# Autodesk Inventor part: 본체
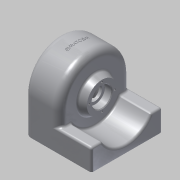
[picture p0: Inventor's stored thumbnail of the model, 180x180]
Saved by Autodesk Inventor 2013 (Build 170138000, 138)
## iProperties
Created: 2015-02
Part Number: 본체
Material: 알루미늄 6061
Document SubType Name: Modeling
Designer: Administrator
Density: 1 g/cm^3
Author: Administrator
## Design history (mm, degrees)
sketch "스케치1"
  geometry: L1 (-34.5, 0)-(34.5, 0); L2 (-34.5, 14)-(-34.5, 21.36); L3 (-34.5, 21.36)-(-24.5, 25); L4 (-24.5, 25)-(-24.5, 50); L5 (-24.5, 50)-(25.5, 50); L6 (25.5, 50)-(25.5, 20); L7 (25.5, 20)-(34.5, 20); L8 (34.5, 20)-(34.5, 0); L9 (34.5, 0)-(31.5, 0); L10 (31.5, 0)-(31.5, 10); L11 (31.5, 10)-(29.5, 10); L12 (29.5, 10)-(29.5, 14); L13 (29.5, 14)-(21.5, 14); L14 (21.5, 14)-(21.5, 46); L15 (21.5, 46)-(-20.5, 46); L16 (-20.5, 46)-(-20.5, 10); L17 (-20.5, 10)-(-24.5, 10); L18 (-24.5, 10)-(-24.5, 14); L19 (-24.5, 14)-(-34.5, 14); 3 further points
  constraints: 38 end point, 9 parallel, 4 perpendicular, 2 coincident, 2 horizontal, 2 midpoint, 1 collinear, 1 point on line, 1 vertical, 1 vertical alignment
  dimensions: "d0" = 69 distance of L1.start L1.end; "d1" = 20 diameter of L17 L1; "d2" = 28 diameter of L19 L1; "d3" = 50 diameter of L3.end L1; "d4" = 100 diameter of L5 L1; "d5" = 10 distance between parallel lines of L2 L4; "d6" = 50 distance of L4.end L5.end; "d7" = 40 diameter of L7 L1; "d8" = 20 diameter of L11 L1; "d9" = 28 diameter of L13 L1; "d10" = 2 distance between parallel lines of L10 L12; "d11" = 8 distance of L12.end L13.end; "d12" = 42 distance of L14.end L15.end; "d13" = 10 distance of L18.end L2.start; "d14" = 4 distance of L16.end L17.end; "d15" = 92 diameter of L15 L1; "d16" = 110 deg angle of L3 L4
revolve "회전1" sketch "스케치1" stored, may be unused: angle "d17" = 90 deg
sketch "스케치3"
  geometry: L1 (0, 50)-(50, 50); L2 (50, 50)-(50, -50); L3 (50, -50)-(0, -50); A1 r 50 centre (0, 0) between (0, 50) and (0, -50) reference
  constraints: 6 end point, 2 point on circle, 2 tangent, 1 horizontal, 1 perpendicular
  dimensions: "d18" = 50 distance of L1.start L1.end; "d19" = 100 distance of L1.end L2.end
extrude "돌출1" join sketch "스케치3" distance "d20" = 50; taper "d21" = 0 deg
sketch "스케치4"
  geometry: L1 (0, 100)-(50, 100) reference; L2 (0, 0)-(0, 100) reference; L3 (4, 96)-(46, 96); L4 (46, 96)-(46, 4); L5 (46, 4)-(4, 4); L6 (4, 4)-(4, 96); 1 further point
  constraints: 8 end point, 2 parallel, 1 horizontal, 1 perpendicular
  dimensions: "d22" = 42 distance of L4.end L5.end; "d23" = 92 distance of L3.end L4.end; "d24" = 4 distance between parallel lines of L2 L6; "d25" = 4 distance between parallel lines of L1 L3
extrude "돌출2" cut sketch "스케치4" distance "d26" = 50; taper "d27" = 0 deg
sketch "스케치5"
  geometry: L1 (-50, 0)-(0, 0) reference; L2 (0, 0)-(0, 100) reference; L3 (0, 100)-(-50, 100) reference; L4 (-30, 84.641)-(-30, 100); L5 (-30, 15.359)-(-30, 0); C1 r 25 at (-50, 50) reference; A1 r 40 centre (-50, 50) between (-30, 15.359) and (-30, 84.641)
  constraints: 4 end point, 2 perpendicular, 2 point on circle, 2 point on line, 1 centre point, 1 coincident, 1 collinear
  dimensions: "d28" = 80 diameter of A1; "d29" = 30 distance between parallel lines of L2 L4
extrude "돌출3" join sketch "스케치5" distance "d30" = 45; taper "d31" = 0 deg
node "작업 평면1"
sketch "스케치6"
  geometry: L1 (-25, 50)-(-25, -50) reference; 2 further points
  constraints: 1 horizontal alignment, 1 other
  dimensions: "d32" = 25 distance from line of L1 point (0, 0)
feature "엠보싱1" sketch "스케치6" dims "d33" = 0.5, "d34" = 0
fillet "모깎기1" dims "d35" = 10
fillet "모깎기2" dims "d36" = 6
fillet "모깎기3" dims "d37" = 0.3
chamfer "모따기1" distance "d38" = 1; stored, may be unused: second distance "d39" = 2, angle "d40" = 45 deg
fillet "모깎기4" dims "d41" = 3
fillet "모깎기5" dims "d42" = 3
fillet "모깎기6" dims "d43" = 3
sketch "스케치7" dims "d44" = 36
  geometry: C1 r 15 at (0, 0) reference; 5 further points
  constraints: 2 vertical alignment, 1 coincident, 7 other
  dimensions: "d47" = 360 deg dimension on point (0, 0) point (0, 18) (derived)
hole "구멍1" sketch "스케치7" at (0, 18), (-18, 0), (0, -18), (18, 0) diameter "d49" = 2.459; stored, may be unused: countersink angle "d53" = 90 deg, drill point angle "d55" = 118 deg; dims "d50" = 6, "d51" = 4, "d52" = 2, "d54" = 9
sketch "스케치8"
  geometry: L1 (-95, -7)-(-95, 87) reference; L2 (-86, 81.75)-(-53, 81.75); L3 (-53, 81.75)-(-53, -1.75); L4 (-53, -1.75)-(-86, -1.75); L5 (-86, -1.75)-(-86, 81.75); 7 further points
  constraints: 8 end point, 4 coincident, 2 midpoint, 2 parallel, 1 horizontal, 1 horizontal alignment, 1 perpendicular
  dimensions: "d56" = 33 distance of L3.end L4.end; "d57" = 83.5 distance of L2.end L3.end; "d58" = 9 distance between parallel lines of L1 L5
hole "구멍2" sketch "스케치8" at (-86, 81.75), (-53, 81.75), (-53, -1.75), (-86, -1.75) diameter "d59" = 5.134; stored, may be unused: countersink angle "d63" = 90 deg, drill point angle "d65" = 118 deg; dims "d60" = 10, "d61" = 4, "d62" = 2, "d64" = 13
node "솔리드1"
